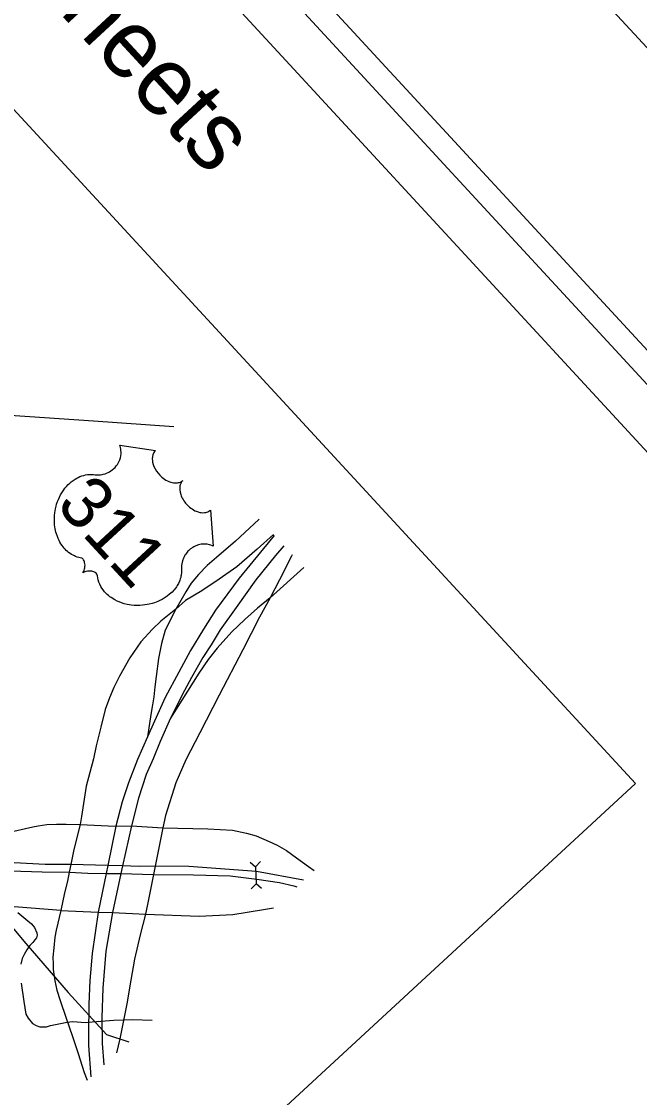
# Model space of a CAD drawing. Extents: x 1695041 to 1706254, y 786537 to 798223.
# Drawn here: x 1703634.1 to 1703837.1, y 796781.2 to 797134.4 of the extents above; entities that cross this region are included whole.
import ezdxf

# ---------------------------------------------------------------- set-up
doc = ezdxf.new("R2010")
doc.units = 0
for name, color, linetype in [('Default', 7, 'Continuous'), ('Old_Level_27', 7, 'Continuous'), ('Old_Level_30', 7, 'Continuous'), ('Old_Level_47', 7, 'Continuous'), ('Sheet Cutting Line CELL', 7, 'Continuous'), ('Sheet Plot Border Inside CELL', 7, 'Continuous'), ('Sheet Plot Border Outside CELL', 7, 'Continuous'), ('Sheet Title CELL', 7, 'Continuous')]:
    doc.layers.add(name, color=color, linetype=linetype)

msp = doc.modelspace()

# ---------------------------------------------------------------- linework, layer by layer
at = {"layer": 'Default'}
for p, q in [((1703835.77, 796884.26), (1703207.65, 797564.73)), ((1703665.16, 796870.23), (1703662.48, 796857.36)), ((1703670.22, 796870.36), (1703667.27, 796857.23)), ((1703680.5, 796869.67), (1703678.06, 796857.14)), ((1703650.31, 796857.69), (1703649.76, 796855.1)), ((1703662.48, 796857.36), (1703661.91, 796854.65)), ((1703667.27, 796857.23), (1703666.77, 796854.67)), ((1703678.06, 796857.14), (1703677.51, 796854.4)), ((1703709.19, 796858.46), (1703710.97, 796856.92)), ((1703712.6, 796858.61), (1703710.97, 796856.92)), ((1703710.97, 796856.92), (1703711.21, 796851.34)), ((1703661.91, 796854.65), (1703659.28, 796841.98)), ((1703666.77, 796854.67), (1703664, 796841.85)), ((1703709.58, 796849.66), (1703711.21, 796851.34)), ((1703712.98, 796849.81), (1703711.21, 796851.34))]:
    msp.add_line(p, q, dxfattribs=at)
for points in [[(1703207.65, 797564.73), (1702636.99, 797037.98), (1703265.12, 796357.5), (1703835.77, 796884.26)], [(1703291.97, 797015.19), (1703324.69, 797005.69), (1703340.9, 797002.01), (1703346.94, 797000.11), (1703357.14, 796996.22), (1703368.85, 796991.59), (1703392.4, 796995.22), (1703415.7, 797000.36), (1703437.39, 797006.05), (1703475.08, 797015.18), (1703510.21, 797012.82), (1703534.98, 797011.35), (1703569.35, 797009.42), (1703597.22, 797007.38), (1703614.23, 797006.26), (1703657.83, 797003.31), (1703684.12, 797001.47)], [(1703712.24, 796971), (1703712.13, 796970.88), (1703704.4, 796963.75), (1703698.13, 796958.46), (1703695.13, 796955.85), (1703692.28, 796952.9), (1703689.87, 796950.02), (1703688.05, 796947.19), (1703684.84, 796941.45)], [(1703414.85, 796967.32), (1703433.69, 796950.61), (1703447.36, 796938.29), (1703454.79, 796931.67), (1703463.03, 796927.76), (1703472.14, 796923.67), (1703478.29, 796921.24), (1703486.59, 796918.81), (1703496.14, 796916.29), (1703507.34, 796914.06), (1703541.09, 796908.09), (1703564.75, 796903.15), (1703577.89, 796899.03), (1703589.73, 796885.57), (1703599.49, 796873.87), (1703614.79, 796855.58), (1703624.36, 796844.92), (1703635.61, 796831.69), (1703649.41, 796815.64), (1703662.09, 796801.81), (1703669.34, 796799.45)], [(1703717.16, 796965.67), (1703716.11, 796964.46), (1703705.62, 796951.69), (1703697.8, 796941.12), (1703693.87, 796934.93), (1703689.6, 796927.87), (1703685.78, 796920.79), (1703681.31, 796912.48), (1703677.76, 796904.66), (1703675.51, 796899.57)], [(1703716.91, 796965.94), (1703711.49, 796961.14), (1703704.82, 796955.36), (1703699.05, 796951.3), (1703693.33, 796947.51), (1703688.04, 796944.33), (1703684.84, 796941.45)], [(1703720.28, 796962.29), (1703717.54, 796959.12), (1703711.05, 796951.1), (1703704.59, 796942.07), (1703699.36, 796934.72), (1703696.4, 796929.76), (1703693.65, 796925.61), (1703689.95, 796919.01), (1703687.68, 796914.79), (1703683.12, 796905.67)], [(1703723.02, 796959.32), (1703722.78, 796958.9), (1703718.84, 796951.16), (1703715.8, 796945.24)], [(1703726.9, 796955.12), (1703715.8, 796945.24)], [(1703715.8, 796945.24), (1703712.31, 796938.81), (1703706.85, 796928.16), (1703699, 796913.25), (1703692.65, 796900.87), (1703688.07, 796892.02), (1703684.78, 796884.46), (1703681.48, 796873.71), (1703680.5, 796869.67)], [(1703715.8, 796945.24), (1703711.62, 796941.85), (1703707.52, 796938.06), (1703703.26, 796934.04), (1703698.4, 796928.68), (1703695.4, 796924.98), (1703692.32, 796920.49), (1703683.12, 796905.67)], [(1703684.84, 796941.45), (1703679.94, 796937.57), (1703677.16, 796934.91), (1703673.36, 796930.72), (1703669.67, 796925.47), (1703666.3, 796919.45), (1703664.49, 796915.73), (1703663.09, 796912.37), (1703661.66, 796908.58), (1703660.2, 796902.79), (1703658.67, 796896.65), (1703657.83, 796892.32), (1703655.42, 796883.34), (1703653.85, 796873.39), (1703653.4, 796870.82)], [(1703684.84, 796941.45), (1703681.34, 796934.6), (1703680.06, 796930.18), (1703679.17, 796925.33), (1703678.39, 796919.39), (1703677.94, 796915.99), (1703677.58, 796912.67), (1703677.16, 796910.05), (1703676.65, 796906.89), (1703675.51, 796899.57)], [(1703683.12, 796905.67), (1703679.72, 796898.07), (1703677.4, 796892.31), (1703675.09, 796887.2), (1703672.56, 796879.42), (1703670.22, 796870.36)], [(1703675.51, 796899.57), (1703672.18, 796892.1), (1703669.32, 796884.52), (1703667.22, 796878.25), (1703665.16, 796870.23)], [(1703653.4, 796870.82), (1703651.37, 796862.63), (1703650.31, 796857.69)], [(1703649.76, 796855.1), (1703649.2, 796852.16), (1703648.29, 796848.4), (1703647.04, 796842.54)], [(1703677.51, 796854.4), (1703675.96, 796846.7), (1703674.82, 796841.3)], [(1703647.04, 796842.54), (1703645.55, 796836.08), (1703645.09, 796833.81), (1703644.75, 796830.31), (1703644.41, 796827.18), (1703644.49, 796825.1), (1703644.58, 796823.18), (1703645.06, 796819.48), (1703645.73, 796816.39), (1703646.85, 796812.99), (1703648.81, 796807.23), (1703650.88, 796801.22), (1703652.71, 796795.59), (1703654.71, 796789.4), (1703655.65, 796786.81)], [(1703659.28, 796841.98), (1703657.31, 796828.49), (1703656.55, 796819.62), (1703656.24, 796811.81), (1703656.17, 796801.83), (1703656.11, 796798.25), (1703656.88, 796787.95)], [(1703664, 796841.85), (1703661.8, 796829.25), (1703660.88, 796817.08), (1703660.5, 796807.45), (1703660.59, 796798.88), (1703661.2, 796791.94)], [(1703674.82, 796841.3), (1703673.09, 796834.62), (1703671.21, 796826.58), (1703670.05, 796819.65), (1703668.78, 796811.92), (1703666.39, 796800.38), (1703665.38, 796795.8)]]:
    msp.add_lwpolyline(points, dxfattribs=at)
msp.add_lwpolyline([(1703678.12, 796993.52), (1703677.86, 796993.24), (1703677.59, 796992.86), (1703677.46, 796992.65), (1703677.27, 796992.18), (1703677.12, 796991.57), (1703677.07, 796990.85), (1703677.11, 796990.14), (1703677.19, 796989.7), (1703677.37, 796989), (1703677.63, 796988.27), (1703678.01, 796987.53), (1703678.44, 796986.81), (1703678.97, 796986.09), (1703679.56, 796985.43), (1703680.26, 796984.78), (1703681.12, 796984.14), (1703681.55, 796983.87), (1703682.05, 796983.6), (1703682.55, 796983.37), (1703683.14, 796983.16), (1703683.65, 796983.03), (1703684.07, 796982.94), (1703684.75, 796982.9), (1703685.38, 796982.94), (1703685.69, 796983.01), (1703685.98, 796983.08), (1703686.53, 796983.32), (1703686.74, 796983.45), (1703687.15, 796983.77), (1703686.85, 796983.45), (1703686.68, 796983.24), (1703686.54, 796983.01), (1703686.41, 796982.74), (1703686.25, 796982.32), (1703686.16, 796981.94), (1703686.08, 796981.3), (1703686.08, 796980.95), (1703686.1, 796980.65), (1703686.21, 796979.89), (1703686.43, 796979.09), (1703686.56, 796978.72), (1703686.72, 796978.36), (1703686.93, 796977.91), (1703687.18, 796977.48), (1703687.45, 796977.07), (1703687.73, 796976.66), (1703688.04, 796976.26), (1703688.31, 796975.95), (1703688.66, 796975.58), (1703688.99, 796975.26), (1703689.36, 796974.95), (1703689.78, 796974.62), (1703690.13, 796974.37), (1703690.62, 796974.06), (1703691.1, 796973.81), (1703691.54, 796973.62), (1703692.15, 796973.4), (1703692.68, 796973.25), (1703693.11, 796973.19), (1703693.66, 796973.14), (1703694.25, 796973.16), (1703694.64, 796973.22), (1703694.99, 796973.33), (1703695.35, 796973.46), (1703695.69, 796973.64), (1703695.96, 796973.83), (1703696.16, 796974.01), (1703697.03, 796962.18), (1703696.82, 796962.28), (1703696.29, 796962.48), (1703695.85, 796962.62), (1703695.09, 796962.78), (1703694.72, 796962.81), (1703694.34, 796962.84), (1703693.97, 796962.84), (1703693.63, 796962.83), (1703693.17, 796962.77), (1703692.74, 796962.7), (1703692.27, 796962.59), (1703691.89, 796962.48), (1703691.15, 796962.18), (1703690.71, 796961.96), (1703690.36, 796961.75), (1703689.68, 796961.27), (1703689.37, 796961.02), (1703689.08, 796960.76), (1703688.79, 796960.47), (1703688.53, 796960.17), (1703688.28, 796959.84), (1703688.06, 796959.54), (1703687.81, 796959.16), (1703687.54, 796958.69), (1703687.31, 796958.2), (1703687.01, 796957.34), (1703686.77, 796956.38), (1703686.7, 796955.78), (1703686.67, 796955.23), (1703686.7, 796954.49), (1703686.71, 796954.07), (1703686.69, 796953.57), (1703686.59, 796952.68), (1703686.51, 796952.29), (1703686.41, 796951.88), (1703686.29, 796951.47), (1703686.15, 796951.04), (1703686.02, 796950.67), (1703685.65, 796949.9), (1703685.25, 796949.2), (1703685.02, 796948.84), (1703684.47, 796948.09), (1703684.18, 796947.74), (1703683.58, 796947.09), (1703682.79, 796946.36), (1703681.99, 796945.72), (1703680.98, 796945.06), (1703680.35, 796944.69), (1703679.58, 796944.31), (1703678.89, 796943.99), (1703677.82, 796943.59), (1703677, 796943.34), (1703676.01, 796943.09), (1703675.38, 796942.97), (1703674.69, 796942.86), (1703673.87, 796942.76), (1703672.96, 796942.7), (1703671.94, 796942.69), (1703671.16, 796942.73), (1703670.19, 796942.82), (1703669.63, 796942.89), (1703668.86, 796943.03), (1703667.86, 796943.28), (1703666.93, 796943.56), (1703666.17, 796943.84), (1703665.54, 796944.12), (1703664.75, 796944.52), (1703663.54, 796945.27), (1703663.13, 796945.56), (1703662.66, 796945.94), (1703662.25, 796946.31), (1703661.86, 796946.68), (1703661.37, 796947.21), (1703660.92, 796947.78), (1703660.53, 796948.34), (1703660.16, 796948.96), (1703659.82, 796949.66), (1703659.56, 796950.33), (1703659.34, 796951.06), (1703659.1, 796952.39), (1703659, 796952.75), (1703658.91, 796952.92), (1703658.62, 796953.26), (1703658.28, 796953.51), (1703657.86, 796953.71), (1703657.59, 796953.81), (1703657.19, 796953.91), (1703656.86, 796953.96), (1703656.42, 796953.99), (1703656.09, 796953.98), (1703655.83, 796953.97), (1703655.23, 796953.86), (1703654.98, 796953.78), (1703654.67, 796953.65), (1703654.26, 796953.42), (1703654.58, 796953.92), (1703654.75, 796954.31), (1703654.86, 796954.68), (1703654.93, 796955.02), (1703654.99, 796955.51), (1703655, 796955.92), (1703654.97, 796956.37), (1703654.88, 796956.8), (1703654.79, 796957.12), (1703654.68, 796957.39), (1703654.51, 796957.69), (1703654.34, 796957.91), (1703654.19, 796958.07), (1703653.93, 796958.25), (1703653.42, 796958.35), (1703652.95, 796958.46), (1703652.46, 796958.6), (1703651.91, 796958.79), (1703651.52, 796958.95), (1703651.09, 796959.16), (1703650.6, 796959.43), (1703650.1, 796959.74), (1703649.62, 796960.1), (1703649.21, 796960.42), (1703648.8, 796960.79), (1703648.45, 796961.15), (1703648.1, 796961.54), (1703647.8, 796961.92), (1703647.45, 796962.37), (1703647.05, 796962.95), (1703646.75, 796963.47), (1703646.46, 796964.03), (1703646.18, 796964.63), (1703645.91, 796965.3), (1703645.61, 796966.17), (1703645.43, 796966.81), (1703645.19, 796967.85), (1703645.01, 796969.16), (1703644.94, 796970.21), (1703644.93, 796971.02), (1703644.99, 796972.28), (1703645.07, 796973.06), (1703645.3, 796974.37), (1703645.5, 796975.27), (1703645.68, 796975.9), (1703646.01, 796976.87), (1703646.24, 796977.45), (1703646.61, 796978.27), (1703646.97, 796978.98), (1703647.34, 796979.63), (1703647.59, 796980.03), (1703648.06, 796980.7), (1703648.4, 796981.16), (1703648.9, 796981.76), (1703649.46, 796982.36), (1703650, 796982.88), (1703650.48, 796983.29), (1703651.06, 796983.73), (1703651.71, 796984.16), (1703652.3, 796984.51), (1703652.74, 796984.73), (1703653.3, 796984.98), (1703653.95, 796985.22), (1703654.61, 796985.41), (1703655.19, 796985.55), (1703655.84, 796985.65), (1703656.43, 796985.7), (1703657.13, 796985.7), (1703657.81, 796985.66), (1703658.38, 796985.57), (1703659.14, 796985.54), (1703659.56, 796985.55), (1703660.11, 796985.6), (1703660.6, 796985.68), (1703661.01, 796985.77), (1703661.61, 796985.93), (1703662.02, 796986.08), (1703662.62, 796986.35), (1703663.02, 796986.57), (1703663.51, 796986.87), (1703663.95, 796987.18), (1703664.45, 796987.61), (1703664.85, 796988), (1703665.27, 796988.48), (1703665.64, 796988.99), (1703665.93, 796989.46), (1703666.23, 796990.05), (1703666.42, 796990.51), (1703666.62, 796991.18), (1703666.77, 796991.85), (1703666.83, 796992.47), (1703666.85, 796993.05), (1703666.81, 796993.55), (1703666.76, 796994.01), (1703666.65, 796994.55), (1703666.5, 796995.03), (1703666.39, 796995.32)], close=True, dxfattribs=at)
at = {"layer": 'Old_Level_27'}
for points in [[(1703548.53, 796871.37), (1703566.06, 796865.83), (1703570.71, 796864.5), (1703575.31, 796863), (1703579.65, 796861.89), (1703584.08, 796860.85), (1703587.47, 796859.94), (1703593.9, 796858.6), (1703598.58, 796857.87), (1703611.75, 796856.13), (1703623.45, 796855.82), (1703640.92, 796855.28), (1703649.76, 796855.1)], [(1703650.31, 796857.69), (1703641.96, 796857.69), (1703627.68, 796858.45), (1703619.04, 796858.36), (1703605.35, 796859.39), (1703598.85, 796860.35), (1703588.44, 796862.27), (1703585.42, 796863.18), (1703582.51, 796864)], [(1703662.48, 796857.36), (1703650.31, 796857.69)], [(1703667.27, 796857.23), (1703662.48, 796857.36)], [(1703678.06, 796857.14), (1703672.81, 796857.01), (1703667.27, 796857.23)], [(1703726.76, 796852.46), (1703711.33, 796855.36), (1703689.06, 796857.01), (1703678.06, 796857.14)], [(1703649.76, 796855.1), (1703655.91, 796854.81), (1703661.91, 796854.65)], [(1703661.91, 796854.65), (1703666.77, 796854.67)], [(1703666.77, 796854.67), (1703677.51, 796854.4)], [(1703677.51, 796854.4), (1703690.61, 796854.24), (1703702.63, 796853.92), (1703711.45, 796852.87), (1703718.89, 796851.72), (1703723.54, 796850.68), (1703724.5, 796850.37)]]:
    msp.add_lwpolyline(points, dxfattribs=at)
at = {"layer": 'Old_Level_30'}
for points in [[(1703632.96, 796841.93), (1703636.22, 796839.2), (1703637.39, 796838.13), (1703638.4, 796836.92), (1703639.21, 796835.22), (1703639.27, 796834.45), (1703639.02, 796833.54), (1703638.52, 796832.9), (1703637.81, 796832.1), (1703636.86, 796831.02), (1703635.88, 796829.66), (1703635.05, 796828.14), (1703634.34, 796826.84), (1703633.96, 796824.93)], [(1703634.04, 796818.65), (1703634.9, 796812.64), (1703635.6, 796808.56), (1703636.31, 796807.22), (1703637.73, 796805.48), (1703638.95, 796804.78), (1703640.11, 796804.39), (1703641.15, 796804.39), (1703642.3, 796804.39), (1703643.7, 796804.77), (1703648.6, 796805.8), (1703650.83, 796806.15), (1703652.45, 796805.96), (1703655.02, 796805.82), (1703657.36, 796806.02), (1703664.41, 796806.55), (1703670.56, 796806.72), (1703677.04, 796806.56)]]:
    msp.add_lwpolyline(points, dxfattribs=at)
at = {"layer": 'Old_Level_47'}
for p, q in [((1703665.16, 796870.23), (1703670.22, 796870.36)), ((1703670.22, 796870.36), (1703680.5, 796869.67)), ((1703647.04, 796842.54), (1703659.28, 796841.98)), ((1703659.28, 796841.98), (1703664, 796841.85))]:
    msp.add_line(p, q, dxfattribs=at)
for points in [[(1703629.24, 796868), (1703637.87, 796870.01), (1703639.56, 796870.31), (1703642.43, 796870.76), (1703645.58, 796870.92), (1703648.85, 796870.95), (1703653.4, 796870.82)], [(1703653.4, 796870.82), (1703662.55, 796870.35), (1703665.16, 796870.23)], [(1703680.5, 796869.67), (1703695.38, 796869.34), (1703703.4, 796868.91), (1703708.04, 796867.91), (1703711.18, 796867.02), (1703715.46, 796865.19), (1703718.15, 796863.99), (1703721.14, 796862.27), (1703724.47, 796859.85), (1703728.4, 796857), (1703730.28, 796855.71)], [(1703647.04, 796842.54), (1703627.54, 796844.07), (1703621.08, 796845.48), (1703609.29, 796848.12)], [(1703664, 796841.85), (1703670.59, 796841.57), (1703674.82, 796841.3)], [(1703674.82, 796841.3), (1703692.5, 796840.71), (1703703.59, 796841.21), (1703713.56, 796842.92), (1703716.93, 796843.38)]]:
    msp.add_lwpolyline(points, dxfattribs=at)
at = {"layer": 'Sheet Cutting Line CELL'}
msp.add_line((1702826.93, 798222.79), (1706253.58, 794510.54), dxfattribs=at)
at = {"layer": 'Sheet Plot Border Inside CELL'}
msp.add_lwpolyline([(1700478.01, 796001.5), (1703869.05, 792327.83), (1706194.94, 794474.78), (1702803.9, 798148.45)], close=True, dxfattribs=at)
at = {"layer": 'Sheet Plot Border Outside CELL'}
msp.add_lwpolyline([(1706253.58, 794510.54), (1702826.93, 798222.79), (1700402.1, 795984.5), (1703828.75, 792272.26)], close=True, dxfattribs=at)
at = {"layer": 'Sheet Title CELL'}
for points in [[(1706143.56, 794519.16), (1703131.99, 797781.79)], [(1706122.34, 794520.04), (1703232.91, 797650.29)]]:
    msp.add_lwpolyline(points, dxfattribs=at)

# ---------------------------------------------------------------- texts
at = {"layer": 'Default'}
msp.add_text('311', height=17.033, rotation=312.7091, dxfattribs=at).set_placement((1703645.09, 796975.37))
at = {"layer": 'Sheet Title CELL'}
msp.add_text('See Sheet 1-A For Index of Sheets', height=22.5, rotation=312.7091, dxfattribs=at).set_placement((1703379.74, 797426.2))

doc.saveas('drawing.dxf')
